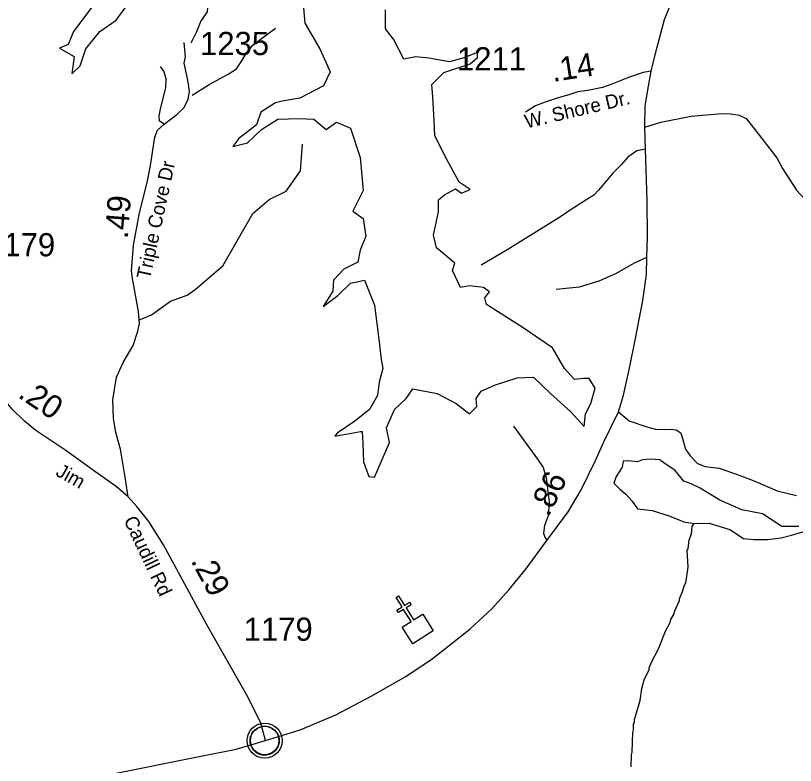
# Model space of a CAD drawing. Extents: x 1248089 to 1457196, y 820910 to 988753.
# Drawn here: x 1328755 to 1332957, y 863432 to 867474 of the extents above; entities that cross this region are included whole.
import ezdxf

# ---------------------------------------------------------------- set-up
doc = ezdxf.new("R2010")
doc.units = 0
for name, color, linetype in [('Exist Civil Demographics Community CELL', 7, 'Continuous'), ('Exist Cultural Church CELL', 7, 'Continuous'), ('Exist Hydrographic Misc Water Feature', 7, 'Continuous'), ('Exist Hydrographic Reservoir', 7, 'Continuous'), ('Exist Road Non-System Type 51', 7, 'Continuous'), ('Exist Road Primary NC Attributed', 7, 'Continuous'), ('Exist Road Secondary Type 41 Attributed', 7, 'Continuous'), ('Exist Road Secondary Type 51 Attributed', 7, 'Continuous'), ('Exist Road Secondary Type 51 Label', 7, 'Continuous'), ('Prop CMT Slope Fill', 7, 'Continuous'), ('Prop GRAU CAT1 Cell', 7, 'Continuous'), ('Prop Lane Lines', 7, 'Continuous')]:
    doc.layers.add(name, color=color, linetype=linetype)

msp = doc.modelspace()

# ---------------------------------------------------------------- linework, layer by layer
at = {"layer": 'Exist Civil Demographics Community CELL'}
msp.add_lwpolyline([(1330019.6, 863577.9), (1330020.6, 863583.5), (1330022.4, 863590.1), (1330025.3, 863597.3), (1330028.2, 863603), (1330031.5, 863608.8), (1330035.3, 863613.9), (1330039.3, 863618.2), (1330043.9, 863622.8), (1330049.4, 863627.4), (1330054.8, 863631.1), (1330059.7, 863634), (1330064.7, 863636.4), (1330070.2, 863638.7), (1330075.8, 863640.5), (1330080.2, 863641.7), (1330085, 863642.4), (1330089.1, 863643.1), (1330095.5, 863643.4), (1330099.9, 863643.3), (1330105.6, 863643), (1330110.5, 863642.3), (1330115.4, 863641.3), (1330120.4, 863639.9), (1330125.6, 863638), (1330132.2, 863635.1), (1330138.5, 863631.6), (1330143.6, 863628), (1330148.7, 863624), (1330152, 863620.9), (1330156.2, 863616.5), (1330160, 863611.8), (1330163.1, 863607.2), (1330166.2, 863602.2), (1330168.7, 863597), (1330170.7, 863592), (1330172.3, 863587), (1330173.6, 863582.4), (1330174.7, 863576.3), (1330175.3, 863571.7), (1330175.5, 863565.7), (1330175.4, 863559.9), (1330174.8, 863554.2), (1330173.9, 863548.7), (1330172.2, 863542.5), (1330170.3, 863536.7), (1330168, 863531.6), (1330164.9, 863525.6), (1330161.6, 863520.3), (1330158.1, 863515.6), (1330153.9, 863510.9), (1330148.6, 863505.9), (1330143.6, 863501.8), (1330138.6, 863498.3), (1330134.3, 863495.8), (1330127.5, 863492.6), (1330120.3, 863489.9), (1330114.4, 863488.4), (1330107.8, 863487.1), (1330103.3, 863486.7), (1330098.8, 863486.4), (1330093.3, 863486.4), (1330089, 863486.8), (1330083.3, 863487.5), (1330077.4, 863488.8), (1330072.8, 863490.2), (1330067.7, 863492), (1330063.1, 863494), (1330059.2, 863496.3), (1330052.4, 863500.3), (1330046.8, 863504.6), (1330041.9, 863509.1), (1330037.4, 863513.9), (1330034.2, 863517.9), (1330031.2, 863522.1), (1330027.2, 863529.2), (1330025.4, 863532.7), (1330023.7, 863536.7), (1330021.1, 863544.9), (1330019.6, 863552), (1330018.9, 863557.1), (1330018.6, 863563.5), (1330018.5, 863568.2), (1330019.1, 863574.6)], close=True, dxfattribs=at)
for centre, radius in [((1330097.2, 863565.5), 94.3), ((1330096.9, 863565.8), 76.7)]:
    msp.add_circle(centre, radius, dxfattribs=at)
at = {"layer": 'Exist Cultural Church CELL'}
msp.add_lwpolyline([(1330838.2, 864177.6), (1330886.4, 864208), (1330845.8, 864272.4), (1330818.7, 864255.4), (1330810.2, 864268.9), (1330837.3, 864285.9), (1330805.3, 864336.8), (1330818.8, 864345.4), (1330850.9, 864294.5), (1330878, 864311.5), (1330886.5, 864298), (1330859.4, 864280.9), (1330899.9, 864216.5), (1330948.8, 864247.1), (1331005.5, 864157), (1330894.9, 864087.5)], close=True, dxfattribs=at)
at = {"layer": 'Exist Hydrographic Misc Water Feature'}
for points in [[(1332379.1, 864500.6), (1332374.9, 864592), (1332379.1, 864599.9), (1332384.2, 864647.7), (1332396.9, 864679.4), (1332401.8, 864719.3), (1332412.5, 864735.2)], [(1332072.4, 863423.3), (1332074, 863489.2), (1332078.3, 863503.1), (1332080.6, 863609), (1332084.9, 863622.9), (1332085.6, 863654.9), (1332089.8, 863662.8), (1332090.3, 863678.8), (1332120.6, 863782.1), (1332130, 863845.9), (1332143.1, 863893.6), (1332168.4, 863948.9), (1332168.5, 863956.9), (1332181.2, 863988.6), (1332218.8, 864059.7), (1332257, 864154.8), (1332282.1, 864202.3), (1332286.5, 864218.1), (1332303.2, 864249.7), (1332307.5, 864265.6), (1332332.7, 864321), (1332332.9, 864329), (1332349.8, 864368.6), (1332358.6, 864400.3), (1332367, 864416.2), (1332379.1, 864500.6)]]:
    msp.add_lwpolyline(points, dxfattribs=at)
at = {"layer": 'Exist Hydrographic Reservoir'}
for points in [[(1329165.3, 867519.2), (1329066.2, 867389.5), (1329038.4, 867318.1), (1328990.9, 867298.3), (1329070.1, 867254.7), (1329058.2, 867159.5), (1329101.8, 867203.1), (1329133.5, 867294.3), (1329208.8, 867389.5), (1329296, 867449), (1329399, 867591.8)], [(1330306.5, 867516.4), (1330314.4, 867433.1), (1330393.7, 867294.3), (1330449.2, 867171.4), (1330413.5, 867096.1), (1330286.7, 867028.6), (1330191.6, 867012.8), (1330155.9, 867004.8), (1330076.7, 866953.3), (1330052.9, 866885.9), (1330004.8, 866847.7), (1329957.3, 866812), (1329925.6, 866768.4)], [(1329925.6, 866768.4), (1330004.8, 866788.2), (1330080.1, 866859.6), (1330167.3, 866915.1), (1330282.2, 866919.1), (1330361.5, 866915.1), (1330428.8, 866859.6), (1330484.3, 866899.3), (1330559.6, 866867.6), (1330611.1, 866708.9), (1330627, 866530.5), (1330571.5, 866419.4), (1330627, 866379.8), (1330642.8, 866284.6), (1330611.1, 866209.3), (1330599.2, 866145.8), (1330523.3, 866107.9), (1330467.8, 866048.4), (1330463.8, 865988.9), (1330412.3, 865905.6), (1330491.6, 865965.1), (1330558.9, 866032.5), (1330634.2, 866048.4), (1330689.7, 865913.6), (1330713.5, 865715.3), (1330725.4, 865620.1), (1330733.3, 865572.5), (1330713.5, 865497.2), (1330705.6, 865425.8), (1330662, 865350.5), (1330582.7, 865287), (1330487.6, 865223.6), (1330475.7, 865207.7), (1330614.4, 865231.5), (1330622.3, 865231.5), (1330626.3, 865168), (1330630.3, 865068.9), (1330658, 864989.6), (1330689.7, 864985.6), (1330725.4, 865068.9), (1330769, 865172), (1330753.1, 865251.3), (1330796.7, 865350.5), (1330860.1, 865409.9), (1330895.8, 865461.5), (1331026.5, 865437.7), (1331129.6, 865382.2), (1331200.9, 865326.7), (1331240.5, 865366.3), (1331236.6, 865409.9), (1331264.3, 865449.6), (1331335.6, 865481.3), (1331458.5, 865521), (1331545.7, 865524.9), (1331636.8, 865437.7), (1331747.8, 865338.6), (1331819.1, 865259.2), (1331827, 865326.7), (1331854.7, 865382.2), (1331878.5, 865465.5), (1331846.8, 865517), (1331815.1, 865517), (1331767.6, 865513), (1331712.1, 865572.5), (1331648.7, 865683.6), (1331490.2, 865790.6), (1331292, 865917.5), (1331284.1, 865953.2), (1331307.9, 865984.9), (1331276.2, 866008.7), (1331200.9, 866016.7), (1331153.3, 866008.7), (1331109.8, 866099.9), (1331121.6, 866139.6), (1331022.6, 866222.9), (1331006.7, 866290.3), (1331034.5, 866417.2), (1331034.5, 866480.6), (1331066.2, 866508.4), (1331125.6, 866540.1), (1331157.3, 866516.3), (1331204.9, 866536.2), (1331145.4, 866575.8), (1331078.1, 866698.7), (1331014.7, 866825.6), (1331010.7, 866908.9), (1331002.8, 867035.8), (1330998.8, 867103.2), (1331062.2, 867166.7), (1331204.9, 867214.3), (1331243.7, 867248), (1331243.7, 867275.8), (1331164.5, 867244), (1331093.1, 867224.2), (1330982.2, 867244), (1330910.9, 867252), (1330847.4, 867240.1), (1330792, 867347.1), (1330748.4, 867402.7), (1330748.4, 867505.8)], [(1332029.7, 865071.2), (1332023.8, 865038.8), (1331991.4, 864988.7), (1331979.6, 864953.3), (1332012, 864920.9), (1332044.4, 864894.4), (1332076.8, 864856.1), (1332106.2, 864814.8), (1332185.7, 864806), (1332277, 864776.5), (1332356.6, 864744.1), (1332412.5, 864735.2), (1332492, 864738.2), (1332603.9, 864702.8), (1332677.6, 864655.7), (1332733.5, 864649.8), (1332807.2, 864649.8), (1332880.8, 864658.6), (1332936.7, 864673.3), (1333028, 864699.9)], [(1332975, 864720.5), (1332883.7, 864720.5), (1332780.6, 864788.3), (1332668.7, 864808.9), (1332550.9, 864862), (1332444.9, 864926.8), (1332394.8, 864950.4), (1332356.6, 864965.1), (1332309.4, 865021.1), (1332247.6, 865062.4), (1332227, 865080.1), (1332176.9, 865083), (1332132.7, 865080.1), (1332106.2, 865068.3), (1332053.2, 865074.2), (1332029.7, 865071.2)]]:
    msp.add_lwpolyline(points, dxfattribs=at)
at = {"layer": 'Exist Road Non-System Type 51'}
for points in [[(1329700.3, 867328.4), (1329730.9, 867389.5), (1329753.1, 867442.3), (1329789.2, 867495.1), (1329792, 867545.2)], [(1329705.9, 867044.8), (1329797.5, 867103.2), (1329900.3, 867158.8), (1329944.7, 867186.6), (1329969.7, 867225.5), (1329992, 867261.6), (1330033.6, 867314.5), (1330080.8, 867350.6), (1330155.8, 867406.2)], [(1329555.7, 866888.5), (1329530.9, 866905.9), (1329528.1, 866933.7), (1329536.4, 866969.8), (1329564.2, 867086.5), (1329567, 867133.8), (1329553.1, 867175.5), (1329536.4, 867200.5)], [(1332145.3, 866872.8), (1332231.7, 866900.3), (1332395.7, 866931.4), (1332497.5, 866941.8), (1332563, 866946.9), (1332609.6, 866945.2), (1332654.5, 866938.3), (1332692.4, 866919.3), (1332739, 866860.6), (1332858.1, 866706.9), (1332887.4, 866649.9), (1332963.4, 866532.5), (1333085.1, 866400.2), (1333117.9, 866353.5), (1333143.8, 866287.9), (1333173.1, 866194.7), (1333197.2, 866146.3), (1333230, 866108.4), (1333268, 866089.4), (1333321.5, 866060), (1333387.1, 865970.2), (1333433.4, 865901.7), (1333447.2, 865870.7)], [(1329421.9, 865834.7), (1329487.7, 865860.3), (1329590.1, 865935.3), (1329679.7, 865966.4), (1329721.8, 865997.5), (1329871.7, 866125.6), (1330032.6, 866407.4), (1330121.5, 866483), (1330212.9, 866526.9), (1330289.7, 866636.7), (1330300.7, 866781.2)], [(1332149.1, 866754.7), (1332102.5, 866745.3), (1332054.2, 866710.8), (1332017.9, 866669.3), (1331973.1, 866624.4), (1331936.8, 866581.3), (1331897.1, 866532.9), (1331871.3, 866507), (1331833.3, 866482.8), (1331738.4, 866422.4), (1331691.8, 866389.6), (1331398.5, 866208.3), (1331263.9, 866128.8)], [(1331667.6, 865998.6), (1331793.6, 866012.4), (1331898.9, 866043.5), (1331990.3, 866083.2), (1332093.8, 866143.6), (1332156, 866171.3)], [(1332004.1, 865338.2), (1332060.8, 865290), (1332157.4, 865257.2), (1332204, 865245.1), (1332252.3, 865243.4), (1332286.8, 865245.1), (1332314.5, 865241.7), (1332340.3, 865224.4), (1332349, 865195), (1332364.5, 865136.3), (1332390.4, 865100.1), (1332430.1, 865058.6), (1332471.5, 865043.1), (1332547.4, 865034.4), (1332654.4, 864996.5), (1332738.9, 864963.6), (1332859.7, 864911.8), (1332963.2, 864887.7)], [(1331438, 865260), (1331567.1, 865083.7), (1331598.5, 865038.3), (1331614.2, 864982.4), (1331629.9, 864853.3), (1331624.6, 864776.5), (1331605.5, 864725.9), (1331600.2, 864684), (1331607.2, 864663.1), (1331617.7, 864643.9)]]:
    msp.add_lwpolyline(points, dxfattribs=at)
at = {"layer": 'Exist Road Primary NC Attributed'}
for points in [[(1332179.9, 867175.4), (1332208.6, 867290.8), (1332251.2, 867453.5), (1332301.5, 867579.3), (1332355.7, 867691.6), (1332452.4, 867860.1), (1332565.4, 868015.8), (1332679.6, 868141.7), (1332795.7, 868257.8), (1332885.9, 868327.9)], [(1331924.8, 865175.6), (1332004.1, 865338.2), (1332031.2, 865427.3), (1332064.1, 865572.6), (1332095, 865733.3), (1332135.6, 865938.7), (1332154.9, 866078.2), (1332156, 866171.3), (1332160.8, 866281.5), (1332158.8, 866477.1), (1332149.1, 866754.7), (1332145.3, 866872.8), (1332147.2, 866987), (1332166.5, 867093.5), (1332179.9, 867175.4)], [(1330101.8, 863565.2), (1330289.2, 863623), (1330480.8, 863704.3), (1330670.4, 863805), (1330858.1, 863911.5), (1330999.3, 864006.4), (1331091.3, 864079.1), (1331205.4, 864168.2), (1331321.5, 864276.7), (1331414.4, 864379.3), (1331505.3, 864489.7), (1331617.7, 864643.9), (1331733.1, 864798.2), (1331802.8, 864918.3), (1331880.2, 865075.1), (1331924.8, 865175.6)], [(1327366.2, 862992.5), (1328027, 863130.4), (1328303.4, 863189.9), (1328782.2, 863286.5), (1329260.1, 863383.1), (1329734.8, 863478.4), (1329942.8, 863519.2), (1330101.8, 863565.2)]]:
    msp.add_lwpolyline(points, dxfattribs=at)
at = {"layer": 'Exist Road Secondary Type 41 Attributed'}
msp.add_lwpolyline([(1329362.1, 864880.4), (1329345.8, 864986.4), (1329320.4, 865137.1), (1329295, 865226.2), (1329282.2, 865304.7), (1329278, 865402.3), (1329299.2, 865525.3), (1329335.2, 865604.7), (1329388.2, 865695.9), (1329413.7, 865772.3), (1329422.1, 865816.8), (1329417.9, 865878.4), (1329384, 866056.6), (1329379.7, 866099), (1329390.3, 866236.9), (1329422.1, 866411.2), (1329464.5, 866574.5), (1329481.5, 866665.8), (1329504.8, 866818.5), (1329519.6, 866856.7), (1329555.7, 866888.5), (1329623.5, 866941.6), (1329661.7, 866977.7), (1329685, 867022.2), (1329691.3, 867066.8), (1329682.9, 867126.2), (1329663.8, 867217.4), (1329670, 867252.2), (1329663.5, 867329.3)], dxfattribs=at)
at = {"layer": 'Exist Road Secondary Type 51 Attributed'}
for points in [[(1332179.9, 867175.4), (1332137.5, 867167.9), (1332058.2, 867140.8), (1331967.3, 867104), (1331917, 867086.6), (1331847.3, 867073), (1331785.4, 867063.4), (1331737, 867047.9), (1331679, 867030.4), (1331609.3, 867007.2), (1331557.1, 866987.8), (1331502.9, 866953)], [(1329362.1, 864880.4), (1329296.9, 864934.7), (1329186.7, 865013.2), (1329025.5, 865129.9), (1328864.4, 865238.1), (1328802.9, 865286.9), (1328735.1, 865354.8), (1328677.8, 865426.9), (1328629.1, 865509.6), (1328580.3, 865594.5)], [(1330101.8, 863565.2), (1330075.9, 863660), (1330008.1, 863797.9), (1329783.3, 864192.6), (1329552.5, 864620.4), (1329472.4, 864746.8), (1329408.8, 864827.4), (1329362.1, 864880.4)]]:
    msp.add_lwpolyline(points, dxfattribs=at)

# ---------------------------------------------------------------- texts
at = {"layer": 'Exist Road Secondary Type 51 Label'}
for s, rotation, p in [('W. Shore Dr.', 13.2532, (1331508.1, 866865.7)), ('Triple Cove Dr', 77.8599, (1329479, 866049.1)), ('Jim ', 330.5308, (1328965.8, 864997.3)), ('Caudill Rd', 295.3032, (1329335.3, 864754.7))]:
    msp.add_text(s, height=75, rotation=rotation, dxfattribs=at).set_placement(p)
at = {"layer": 'Prop CMT Slope Fill'}
msp.add_text('.86', height=125, rotation=63.7363, dxfattribs=at).set_placement((1331627.3, 864767.9))
at = {"layer": 'Prop GRAU CAT1 Cell'}
for s, rotation, p in [('.14', 8.8871, (1331650.8, 867116.7)), ('.49', 85.605, (1329359.2, 866268.6)), ('.20', 326.1155, (1328761.6, 865419.8)), ('.29', 298.346, (1329696.5, 864535.1))]:
    msp.add_text(s, height=125, rotation=rotation, dxfattribs=at).set_placement(p)
at = {"layer": 'Prop Lane Lines'}
for s, p in [('1235', (1329748.9, 867261.6)), ('1211', (1331133.7, 867179)), ('1179', (1328596, 866176.5)), ('1179', (1329984.1, 864103.6))]:
    msp.add_text(s, height=125, dxfattribs=at).set_placement(p)

doc.saveas('drawing.dxf')
